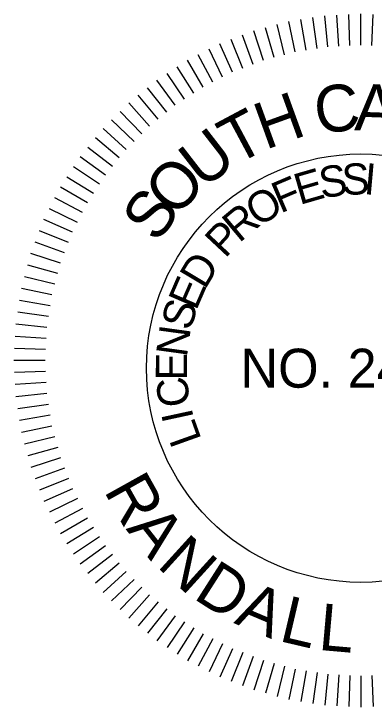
# Model space of a CAD drawing. Extents: x 1964849 to 1967422, y 1116563 to 1122211.
# Drawn here: x 1967319.9 to 1967361, y 1117096.1 to 1117175.3 of the extents above; entities that cross this region are included whole.
import ezdxf

# ---------------------------------------------------------------- set-up
doc = ezdxf.new("R2010")
doc.units = 0
doc.layers.add('RD_TX_PEShield', color=7, linetype='Continuous')

msp = doc.modelspace()

# ---------------------------------------------------------------- linework, layer by layer
at = {"layer": 'RD_TX_PEShield'}
for p, q in [((1967353.287, 1117171.182), (1967352.669, 1117174.683)), ((1967353.287, 1117171.182), (1967352.669, 1117174.683)), ((1967354.528, 1117171.378), (1967354.033, 1117174.899)), ((1967354.528, 1117171.378), (1967354.033, 1117174.899)), ((1967355.77, 1117171.575), (1967355.398, 1117175.115)), ((1967355.77, 1117171.575), (1967355.398, 1117175.115)), ((1967357.027, 1117171.641), (1967356.779, 1117175.188)), ((1967357.027, 1117171.641), (1967356.779, 1117175.188)), ((1967358.282, 1117171.707), (1967358.158, 1117175.26)), ((1967358.282, 1117171.707), (1967358.158, 1117175.26)), ((1967359.538, 1117171.772), (1967359.538, 1117175.332)), ((1967359.538, 1117171.772), (1967359.538, 1117175.332)), ((1967360.794, 1117171.707), (1967360.919, 1117175.26)), ((1967360.794, 1117171.707), (1967360.919, 1117175.26)), ((1967350.829, 1117170.659), (1967349.968, 1117174.109)), ((1967350.829, 1117170.659), (1967349.968, 1117174.109)), ((1967352.044, 1117170.985), (1967351.304, 1117174.467)), ((1967352.044, 1117170.985), (1967351.304, 1117174.467)), ((1967348.4, 1117170.008), (1967347.299, 1117173.394)), ((1967348.4, 1117170.008), (1967347.299, 1117173.394)), ((1967349.615, 1117170.334), (1967348.635, 1117173.752)), ((1967349.615, 1117170.334), (1967348.635, 1117173.752)), ((1967346.052, 1117169.107), (1967344.72, 1117172.404)), ((1967346.052, 1117169.107), (1967344.72, 1117172.404)), ((1967347.225, 1117169.557), (1967346.009, 1117172.899)), ((1967347.225, 1117169.557), (1967346.009, 1117172.899)), ((1967344.877, 1117168.656), (1967343.429, 1117171.908)), ((1967344.877, 1117168.656), (1967343.429, 1117171.908)), ((1967343.756, 1117168.085), (1967342.198, 1117171.281)), ((1967343.756, 1117168.085), (1967342.198, 1117171.281)), ((1967341.516, 1117166.943), (1967339.736, 1117170.026)), ((1967341.516, 1117166.943), (1967339.736, 1117170.026)), ((1967342.637, 1117167.514), (1967340.967, 1117170.654)), ((1967342.637, 1117167.514), (1967340.967, 1117170.654)), ((1967340.46, 1117166.258), (1967338.576, 1117169.273)), ((1967340.46, 1117166.258), (1967338.576, 1117169.273)), ((1967339.406, 1117165.574), (1967337.418, 1117168.521)), ((1967339.406, 1117165.574), (1967337.418, 1117168.521)), ((1967338.351, 1117164.888), (1967336.259, 1117167.769)), ((1967338.351, 1117164.888), (1967336.259, 1117167.769)), ((1967337.374, 1117164.097), (1967335.184, 1117166.899)), ((1967337.374, 1117164.097), (1967335.184, 1117166.899)), ((1967336.397, 1117163.306), (1967334.111, 1117166.03)), ((1967336.397, 1117163.306), (1967334.111, 1117166.03)), ((1967335.419, 1117162.514), (1967333.037, 1117165.16)), ((1967335.419, 1117162.514), (1967333.037, 1117165.16)), ((1967334.53, 1117161.624), (1967332.06, 1117164.182)), ((1967334.53, 1117161.624), (1967332.06, 1117164.182)), ((1967333.641, 1117160.736), (1967331.083, 1117163.206)), ((1967333.641, 1117160.736), (1967331.083, 1117163.206)), ((1967332.751, 1117159.846), (1967330.106, 1117162.228)), ((1967332.751, 1117159.846), (1967330.106, 1117162.228)), ((1967331.96, 1117158.868), (1967329.236, 1117161.154)), ((1967331.96, 1117158.868), (1967329.236, 1117161.154)), ((1967331.169, 1117157.892), (1967328.367, 1117160.081)), ((1967331.169, 1117157.892), (1967328.367, 1117160.081)), ((1967330.377, 1117156.914), (1967327.497, 1117159.007)), ((1967330.377, 1117156.914), (1967327.497, 1117159.007)), ((1967329.692, 1117155.859), (1967326.744, 1117157.847)), ((1967329.692, 1117155.859), (1967326.744, 1117157.847)), ((1967329.007, 1117154.805), (1967325.992, 1117156.689)), ((1967329.007, 1117154.805), (1967325.992, 1117156.689)), ((1967328.322, 1117153.75), (1967325.239, 1117155.53)), ((1967328.322, 1117153.75), (1967325.239, 1117155.53)), ((1967327.751, 1117152.629), (1967324.612, 1117154.298)), ((1967327.751, 1117152.629), (1967324.612, 1117154.298)), ((1967327.18, 1117151.509), (1967323.985, 1117153.068)), ((1967327.18, 1117151.509), (1967323.985, 1117153.068)), ((1967326.609, 1117150.388), (1967323.357, 1117151.836)), ((1967326.609, 1117150.388), (1967323.357, 1117151.836)), ((1967326.158, 1117149.214), (1967322.862, 1117150.546)), ((1967326.158, 1117149.214), (1967322.862, 1117150.546)), ((1967325.708, 1117148.041), (1967322.367, 1117149.257)), ((1967325.708, 1117148.041), (1967322.367, 1117149.257)), ((1967325.257, 1117146.866), (1967321.871, 1117147.966)), ((1967325.257, 1117146.866), (1967321.871, 1117147.966)), ((1967324.932, 1117145.651), (1967321.514, 1117146.631)), ((1967324.932, 1117145.651), (1967321.514, 1117146.631)), ((1967324.606, 1117144.437), (1967321.156, 1117145.297)), ((1967324.606, 1117144.437), (1967321.156, 1117145.297)), ((1967324.281, 1117143.222), (1967320.799, 1117143.962)), ((1967324.281, 1117143.222), (1967320.799, 1117143.962)), ((1967324.084, 1117141.979), (1967320.582, 1117142.596)), ((1967324.084, 1117141.979), (1967320.582, 1117142.596)), ((1967323.887, 1117140.738), (1967320.366, 1117141.233)), ((1967323.887, 1117140.738), (1967320.366, 1117141.233)), ((1967323.691, 1117139.495), (1967320.15, 1117139.867)), ((1967323.691, 1117139.495), (1967320.15, 1117139.867)), ((1967323.625, 1117138.239), (1967320.078, 1117138.487)), ((1967323.625, 1117138.239), (1967320.078, 1117138.487)), ((1967323.559, 1117136.984), (1967320.005, 1117137.108)), ((1967323.559, 1117136.984), (1967320.005, 1117137.108)), ((1967323.493, 1117135.727), (1967319.933, 1117135.727)), ((1967323.493, 1117135.727), (1967319.933, 1117135.727)), ((1967323.559, 1117134.471), (1967320.005, 1117134.347)), ((1967323.559, 1117134.471), (1967320.005, 1117134.347)), ((1967323.625, 1117133.216), (1967320.078, 1117132.968)), ((1967323.625, 1117133.216), (1967320.078, 1117132.968)), ((1967323.691, 1117131.96), (1967320.15, 1117131.588)), ((1967323.691, 1117131.96), (1967320.15, 1117131.588)), ((1967323.887, 1117130.717), (1967320.366, 1117130.222)), ((1967323.887, 1117130.717), (1967320.366, 1117130.222)), ((1967324.084, 1117129.476), (1967320.582, 1117128.858)), ((1967324.084, 1117129.476), (1967320.582, 1117128.858)), ((1967324.281, 1117128.233), (1967320.799, 1117127.493)), ((1967324.281, 1117128.233), (1967320.799, 1117127.493)), ((1967324.606, 1117127.018), (1967321.156, 1117126.158)), ((1967324.606, 1117127.018), (1967321.156, 1117126.158)), ((1967324.932, 1117125.804), (1967321.514, 1117124.824)), ((1967324.932, 1117125.804), (1967321.514, 1117124.824)), ((1967325.257, 1117124.589), (1967321.871, 1117123.489)), ((1967325.708, 1117123.414), (1967322.367, 1117122.198)), ((1967325.708, 1117123.414), (1967322.367, 1117122.198)), ((1967326.158, 1117122.241), (1967322.862, 1117120.909)), ((1967326.158, 1117122.241), (1967322.862, 1117120.909)), ((1967326.609, 1117121.067), (1967323.357, 1117119.619)), ((1967326.609, 1117121.067), (1967323.357, 1117119.619)), ((1967327.18, 1117119.946), (1967323.985, 1117118.387)), ((1967327.18, 1117119.946), (1967323.985, 1117118.387)), ((1967327.751, 1117118.826), (1967324.612, 1117117.157)), ((1967327.751, 1117118.826), (1967324.612, 1117117.157)), ((1967328.322, 1117117.705), (1967325.239, 1117115.925)), ((1967328.322, 1117117.705), (1967325.239, 1117115.925)), ((1967329.007, 1117116.65), (1967325.992, 1117114.766)), ((1967329.007, 1117116.65), (1967325.992, 1117114.766)), ((1967329.692, 1117115.596), (1967326.744, 1117113.608)), ((1967329.692, 1117115.596), (1967326.744, 1117113.608)), ((1967330.377, 1117114.541), (1967327.497, 1117112.448)), ((1967330.377, 1117114.541), (1967327.497, 1117112.448)), ((1967331.169, 1117113.563), (1967328.367, 1117111.374)), ((1967331.169, 1117113.563), (1967328.367, 1117111.374)), ((1967331.96, 1117112.586), (1967329.236, 1117110.301)), ((1967331.96, 1117112.586), (1967329.236, 1117110.301)), ((1967332.751, 1117111.609), (1967330.106, 1117109.227)), ((1967332.751, 1117111.609), (1967330.106, 1117109.227)), ((1967333.641, 1117110.719), (1967331.083, 1117108.249)), ((1967333.641, 1117110.719), (1967331.083, 1117108.249)), ((1967334.53, 1117109.83), (1967332.06, 1117107.273)), ((1967334.53, 1117109.83), (1967332.06, 1117107.273)), ((1967335.419, 1117108.941), (1967333.037, 1117106.295)), ((1967335.419, 1117108.941), (1967333.037, 1117106.295)), ((1967336.397, 1117108.149), (1967334.111, 1117105.425)), ((1967336.397, 1117108.149), (1967334.111, 1117105.425)), ((1967337.374, 1117107.358), (1967335.184, 1117104.556)), ((1967337.374, 1117107.358), (1967335.184, 1117104.556)), ((1967338.351, 1117106.566), (1967336.259, 1117103.686)), ((1967338.351, 1117106.566), (1967336.259, 1117103.686)), ((1967339.406, 1117105.881), (1967337.418, 1117102.933)), ((1967339.406, 1117105.881), (1967337.418, 1117102.933)), ((1967340.46, 1117105.197), (1967338.576, 1117102.181)), ((1967340.46, 1117105.197), (1967338.576, 1117102.181)), ((1967341.516, 1117104.512), (1967339.736, 1117101.428)), ((1967341.516, 1117104.512), (1967339.736, 1117101.428)), ((1967342.637, 1117103.94), (1967340.967, 1117100.801)), ((1967342.637, 1117103.94), (1967340.967, 1117100.801)), ((1967343.756, 1117103.37), (1967342.198, 1117100.174)), ((1967343.756, 1117103.37), (1967342.198, 1117100.174)), ((1967344.877, 1117102.799), (1967343.429, 1117099.546)), ((1967344.877, 1117102.799), (1967343.429, 1117099.546)), ((1967346.052, 1117102.348), (1967344.72, 1117099.051)), ((1967346.052, 1117102.348), (1967344.72, 1117099.051)), ((1967347.225, 1117101.897), (1967346.009, 1117098.556)), ((1967347.225, 1117101.897), (1967346.009, 1117098.556)), ((1967348.4, 1117101.447), (1967347.299, 1117098.061)), ((1967348.4, 1117101.447), (1967347.299, 1117098.061)), ((1967349.615, 1117101.121), (1967348.635, 1117097.703)), ((1967349.615, 1117101.121), (1967348.635, 1117097.703)), ((1967350.829, 1117100.796), (1967349.968, 1117097.346)), ((1967350.829, 1117100.796), (1967349.968, 1117097.346)), ((1967352.044, 1117100.47), (1967351.304, 1117096.988)), ((1967352.044, 1117100.47), (1967351.304, 1117096.988)), ((1967353.287, 1117100.273), (1967352.669, 1117096.772)), ((1967353.287, 1117100.273), (1967352.669, 1117096.772)), ((1967354.528, 1117100.077), (1967354.033, 1117096.556)), ((1967354.528, 1117100.077), (1967354.033, 1117096.556)), ((1967355.77, 1117099.88), (1967355.398, 1117096.339)), ((1967355.77, 1117099.88), (1967355.398, 1117096.339)), ((1967357.027, 1117099.814), (1967356.779, 1117096.267)), ((1967357.027, 1117099.814), (1967356.779, 1117096.267)), ((1967358.282, 1117099.748), (1967358.158, 1117096.195)), ((1967358.282, 1117099.748), (1967358.158, 1117096.195)), ((1967359.538, 1117099.682), (1967359.538, 1117096.122)), ((1967359.538, 1117099.682), (1967359.538, 1117096.122)), ((1967360.794, 1117099.748), (1967360.919, 1117096.195)), ((1967360.794, 1117099.748), (1967360.919, 1117096.195))]:
    msp.add_line(p, q, dxfattribs=at)
msp.add_circle((1967359.538, 1117134.849), 24.475, dxfattribs=at)

# ---------------------------------------------------------------- texts
for s, height, rotation, p in [('C', 5.34, 6.88322, (1967354.532, 1117161.587)), ('A', 5.34, 357.94482, (1967358.747, 1117162.04)), ('H', 5.34, 19.91024, (1967348.634, 1117159.771)), ('T', 5.34, 28.09472, (1967345.197, 1117157.965)), ('U', 5.34, 37.77255, (1967341.516, 1117155.225)), ('O', 5.34, 47.45038, (1967338.347, 1117151.905)), ('S', 3.56, 8.69092, (1967355.026, 1117154.237)), ('S', 3.56, 1.78995, (1967357.388, 1117154.639)), ('I', 3.56, 354.88899, (1967359.782, 1117154.754)), ('E', 3.56, 16.18428, (1967352.536, 1117153.483)), ('F', 3.56, 23.08525, (1967350.348, 1117152.507)), ('S', 5.34, 54.90268, (1967336.314, 1117149.012)), ('O', 3.56, 31.78688, (1967347.782, 1117150.913)), ('R', 3.56, 39.89024, (1967345.635, 1117149.096)), ('P', 3.56, 46.7912, (1967344.024, 1117147.322)), ('D', 3.56, 59.07401, (1967341.726, 1117143.736)), ('E', 3.56, 66.56738, (1967340.719, 1117141.338)), ('S', 3.56, 73.46834, (1967340.076, 1117139.029)), ('N', 3.56, 82.16997, (1967339.667, 1117136.037)), ('E', 3.56, 89.66334, (1967339.682, 1117133.435)), ('C', 3.56, 97.7667, (1967340.08, 1117130.651)), ('I', 3.56, 102.25114, (1967340.468, 1117129.142)), ('L', 3.56, 109.74451, (1967341.375, 1117126.704)), ('R', 5.34, 299.14926, (1967330.136, 1117120.876)), ('A', 5.34, 308.08766, (1967332.664, 1117116.477)), ('N', 5.34, 317.7655, (1967336.135, 1117112.221)), ('D', 5.34, 327.44333, (1967340.272, 1117108.608)), ('A', 5.34, 337.12116, (1967344.958, 1117105.743)), ('L', 5.34, 346.799, (1967350.058, 1117103.706)), ('L', 5.34, 354.98347, (1967354.588, 1117102.674))]:
    msp.add_text(s, height=height, rotation=rotation, dxfattribs=at).set_placement(p)
msp.add_text('NO. 24265', height=4.4501, dxfattribs=at).set_placement((1967345.784, 1117132.624))

doc.saveas('drawing.dxf')
